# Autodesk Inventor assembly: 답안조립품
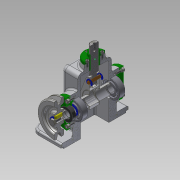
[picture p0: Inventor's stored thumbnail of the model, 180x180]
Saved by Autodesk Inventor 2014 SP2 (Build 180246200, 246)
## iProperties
Created: 2016-08
Part Number: 답안조립품
Document SubType Name: Assembly
Designer: user
Author: user
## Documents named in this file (19)
- C:\Users\user\Desktop\460820V1003\답안조립품.iam
- C:\Users\user\Desktop\460820V1003\본체.ipt
- C:\Users\user\Desktop\460820V1003\V-벨트풀리.ipt
- C:\Users\user\Desktop\460820V1003\고정핀.ipt
- C:\Users\user\Desktop\460820V1003\뒤커버.ipt
- C:\Users\user\Desktop\460820V1003\링크.ipt
- C:\Users\user\Desktop\460820V1003\멈춤링 6 x 5.ipt
- C:\Users\user\Desktop\460820V1003\멈춤링 15 x 1.ipt
- C:\Users\user\Desktop\460820V1003\베어링 15 x 35 x 11.ipt
- C:\Users\user\Desktop\460820V1003\볼트 M3 x 8.ipt
- C:\Users\user\Desktop\460820V1003\볼트 M4 x 10.ipt
- C:\Users\user\Desktop\460820V1003\볼트 M6 x 12.ipt
- C:\Users\user\Desktop\460820V1003\상부부시.ipt
- C:\Users\user\Desktop\460820V1003\슬라이드바.ipt
- C:\Users\user\Desktop\460820V1003\앞커버.ipt
- C:\Users\user\Desktop\460820V1003\오일실 15 25 7.ipt
- C:\Users\user\Desktop\460820V1003\와셔.ipt
- C:\Users\user\Desktop\460820V1003\키 5 x 5 x 14.ipt
- C:\Users\user\Desktop\460820V1003\편심축.ipt
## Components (15 placed, 5 different names)
1. V-벨트풀리:1 — 각도:1
2. 고정핀:1 — 각도:5
3. ISO 4018 M6 x 12:1 — 각도:6, 각도:9, 각도:10
4. ISO 4762 M4 x 10:2 — 강체:3
5. ISO 4762 M4 x 10:1 — 강체:4
6. ISO 4762 M4 x 10:3
7. ISO 4762 M4 x 10:4
8. ISO 4762 M4 x 10:5
9. ISO 4762 M4 x 10:6
10. ISO 4762 M4 x 10:7
11. ISO 4762 M4 x 10:8
12. ISO 4762 M3 x 8:1 — 강체:5
13. ISO 4762 M3 x 8:2
14. ISO 4762 M3 x 8:3
15. ISO 4762 M3 x 8:4
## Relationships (8: Angle 5, WeldJoint 3)
- 각도:1 [Angle]: V-벨트풀리:1
- 강체:3 [WeldJoint]: ISO 4762 M4 x 10:2
- 강체:4 [WeldJoint]: ISO 4762 M4 x 10:1
- 강체:5 [WeldJoint]: ISO 4762 M3 x 8:1
- 각도:5 [Angle]: 고정핀:1
- 각도:6 [Angle]: ISO 4018 M6 x 12:1
- 각도:9 [Angle]: ISO 4018 M6 x 12:1
- 각도:10 [Angle]: ISO 4018 M6 x 12:1
